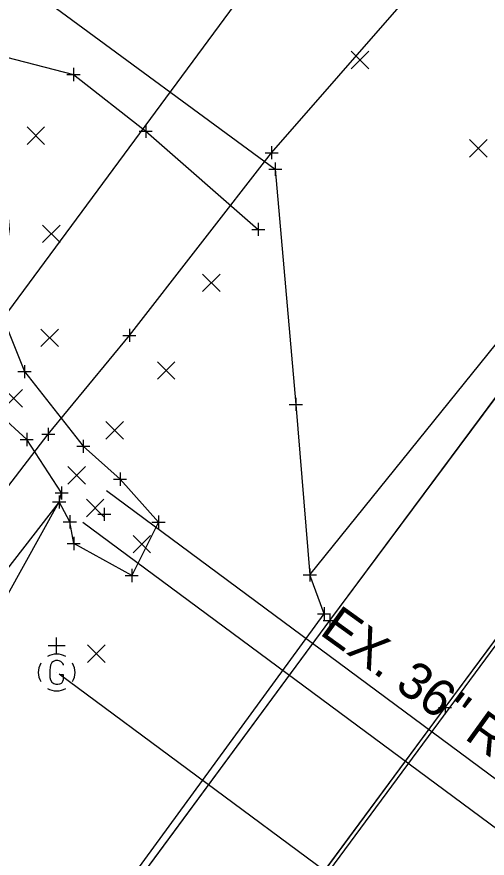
# Model space of a CAD drawing. Extents: x 1324089 to 1329959, y 459099 to 462017.
# Drawn here: x 1325758 to 1325793.8, y 460930.3 to 460994.4 of the extents above; entities that cross this region are included whole.
import ezdxf

# ---------------------------------------------------------------- set-up
doc = ezdxf.new("R2010")
doc.units = 0
for name, color, linetype in [('Default', 7, 'Continuous'), ('DR_X_Storm_Sewer', 7, 'Continuous'), ('PM_X_CL_Double_Solid', 7, 'Continuous'), ('PM_X_Edge_Line', 7, 'Continuous'), ('PM_X_Surveyed_Line', 7, 'Continuous'), ('PV_X_Driveway', 7, 'Continuous'), ('PV_X_EOP', 7, 'Continuous'), ('RW_X_CL', 7, 'Continuous'), ('RW_X_Fee_RW', 7, 'Continuous'), ('SV_X_Break_Lines', 7, 'Continuous'), ('SV_X_Random_Point', 7, 'Continuous'), ('SV_X_Shot_Marker', 7, 'Continuous'), ('UT_X_Gas', 7, 'Continuous'), ('UT_X_Gas_Cells', 7, 'Continuous'), ('UT_X_Telecom', 7, 'Continuous')]:
    doc.layers.add(name, color=color, linetype=linetype)

msp = doc.modelspace()

# ---------------------------------------------------------------- linework, layer by layer
at = {"layer": 'DR_X_Storm_Sewer'}
for p, q in [((1325764.818, 460958.35), (1325814.731, 460921.372)), ((1325763.032, 460955.94), (1325812.945, 460918.961))]:
    msp.add_line(p, q, dxfattribs=at)
at = {"layer": 'PM_X_CL_Double_Solid'}
for p, q in [((1325790.621, 460941.822), (1325811.714, 460970.267)), ((1325771.48, 460915.921), (1325790.621, 460941.822))]:
    msp.add_line(p, q, dxfattribs=at)
at = {"layer": 'PM_X_Edge_Line'}
for p, q in [((1325781.839, 460948.458), (1325803.18, 460977.152)), ((1325762.589, 460922.342), (1325781.839, 460948.458))]:
    msp.add_line(p, q, dxfattribs=at)
at = {"layer": 'PM_X_Surveyed_Line'}
for points in [[(1325476.468, 460534.643), (1325497.311, 460562.916), (1325518.315, 460591.401), (1325539.274, 460619.828), (1325559.79, 460647.383), (1325579.721, 460674.061), (1325600.337, 460701.825), (1325621.689, 460730.614), (1325640.884, 460756.72), (1325660.886, 460784.382), (1325681.351, 460812.314), (1325701.967, 460840.182), (1325722.786, 460868.466), (1325742.91, 460895.719), (1325762.589, 460922.342), (1325781.839, 460948.458), (1325803.18, 460977.152), (1325823.469, 461004.355), (1325843.804, 461031.799), (1325864.413, 461059.129), (1325882.729, 461083.843)], [(1325487.31, 460531.49), (1325505.558, 460556.208), (1325527.376, 460585.354), (1325547.884, 460612.775), (1325568.496, 460640.752), (1325588.531, 460667.691), (1325609.182, 460695.622), (1325629.784, 460723.415), (1325649.854, 460750.691), (1325670.058, 460778.358), (1325689.988, 460805.971), (1325710.726, 460833.831), (1325731.558, 460861.892), (1325751.846, 460889.277), (1325771.48, 460915.921), (1325790.621, 460941.822), (1325811.714, 460970.267), (1325832.154, 460997.962), (1325852.519, 461025.379), (1325872.843, 461052.92), (1325891.559, 461078.179)]]:
    msp.add_lwpolyline(points, dxfattribs=at)
at = {"layer": 'PV_X_Driveway'}
msp.add_lwpolyline([(1325740.02, 461010.738), (1325760.541, 460995.43), (1325777.688, 460982.844), (1325779.255, 460964.921), (1325780.318, 460951.923)], dxfattribs=at)
at = {"layer": 'PV_X_EOP'}
msp.add_lwpolyline([(1325599.851, 460702.278), (1325620.929, 460731.198), (1325640.127, 460757.247), (1325660.195, 460784.818), (1325680.806, 460812.72), (1325701.432, 460840.567), (1325722.312, 460868.776), (1325742.472, 460895.993), (1325762.177, 460922.641), (1325781.401, 460948.968), (1325780.318, 460951.923), (1325801.557, 460978.256), (1325816.225, 460999.305), (1325818.005, 460999.229), (1325822.667, 461005.049), (1325842.969, 461032.462), (1325863.411, 461059.87), (1325881.769, 461084.581), (1325817.824, 460998.906)], dxfattribs=at)
at = {"layer": 'RW_X_CL'}
msp.add_line((1325484.957, 460527.536), (1326057.933, 461303.201), dxfattribs=at)
at = {"layer": 'RW_X_Fee_RW'}
msp.add_line((1325448.762, 460554.274), (1326011.051, 461315.471), dxfattribs=at)
at = {"layer": 'SV_X_Break_Lines'}
for points in [[(1325755.792, 460950.517), (1325747.971, 460958.055), (1325739.888, 460967.035), (1325733.431, 460974.308), (1325738.909, 460981.966), (1325746.102, 460990.388), (1325754.917, 460991.961), (1325762.313, 460990.056), (1325767.82, 460985.73), (1325776.392, 460978.257)], [(1325602.569, 460725.503), (1325611.535, 460737.32), (1325631.624, 460762.971), (1325651.116, 460791.065), (1325670.213, 460817.468), (1325692.281, 460846.55), (1325713.18, 460875.417), (1325733.816, 460902.837), (1325743.825, 460918.052), (1325750.809, 460936.819), (1325754.596, 460945.574), (1325761.22, 460957.492), (1325755.792, 460950.517)]]:
    msp.add_lwpolyline(points, dxfattribs=at)
msp.add_lwpolyline([(1325761.22, 460957.492), (1325761.412, 460958.176), (1325758.753, 460962.25), (1325754.408, 460966.201), (1325747.053, 460971.488), (1325744.168, 460973.186), (1325741.264, 460977.729), (1325743.709, 460980.748), (1325748.637, 460978.595), (1325751.459, 460980.538), (1325750.657, 460983.988), (1325752.818, 460985.149), (1325755.224, 460984.954), (1325757.128, 460981.497), (1325757.411, 460978.28), (1325756.573, 460972.388), (1325758.586, 460967.416), (1325763.061, 460961.728), (1325765.859, 460959.222), (1325768.795, 460955.944), (1325766.752, 460951.889), (1325762.332, 460954.322), (1325762.039, 460955.973)], close=True, dxfattribs=at)
at = {"layer": 'SV_X_Random_Point'}
for p, q in [((1325783.47, 460990.486), (1325784.803, 460991.821)), ((1325783.47, 460991.821), (1325784.803, 460990.486)), ((1325758.778, 460984.721), (1325760.111, 460986.056)), ((1325758.778, 460986.056), (1325760.111, 460984.721)), ((1325792.486, 460983.759), (1325793.819, 460985.094)), ((1325792.486, 460985.094), (1325793.819, 460983.759)), ((1325759.955, 460977.243), (1325761.288, 460978.578)), ((1325759.955, 460978.578), (1325761.288, 460977.243)), ((1325772.153, 460973.517), (1325773.486, 460974.852)), ((1325772.153, 460974.852), (1325773.486, 460973.517)), ((1325759.838, 460969.32), (1325761.172, 460970.655)), ((1325759.838, 460970.655), (1325761.172, 460969.32)), ((1325768.703, 460966.833), (1325770.036, 460968.168)), ((1325768.703, 460968.168), (1325770.036, 460966.833)), ((1325757.085, 460964.722), (1325758.418, 460966.057)), ((1325757.085, 460966.057), (1325758.418, 460964.722)), ((1325764.791, 460962.273), (1325766.125, 460963.608)), ((1325764.791, 460963.608), (1325766.125, 460962.273)), ((1325761.889, 460958.844), (1325763.223, 460960.179)), ((1325761.889, 460960.179), (1325763.223, 460958.844)), ((1325763.303, 460956.367), (1325764.636, 460957.701)), ((1325763.303, 460957.701), (1325764.636, 460956.367)), ((1325766.855, 460953.605), (1325768.188, 460954.94)), ((1325766.855, 460954.94), (1325768.188, 460953.605)), ((1325763.386, 460945.264), (1325764.719, 460946.599)), ((1325763.386, 460946.599), (1325764.719, 460945.264))]:
    msp.add_line(p, q, dxfattribs=at)
at = {"layer": 'SV_X_Shot_Marker'}
for p, q in [((1325762.313, 460990.556), (1325762.313, 460989.556)), ((1325761.813, 460990.056), (1325762.813, 460990.056)), ((1325762.313, 460990.056), (1325762.313, 460990.056)), ((1325767.82, 460986.23), (1325767.82, 460985.23)), ((1325767.32, 460985.73), (1325768.32, 460985.73)), ((1325767.82, 460985.73), (1325767.82, 460985.73)), ((1325776.911, 460984.097), (1325777.911, 460984.097)), ((1325777.411, 460984.597), (1325777.411, 460983.597)), ((1325777.411, 460984.097), (1325777.411, 460984.097)), ((1325777.188, 460982.844), (1325778.188, 460982.844)), ((1325777.688, 460983.344), (1325777.688, 460982.344)), ((1325777.688, 460982.844), (1325777.688, 460982.844)), ((1325775.892, 460978.257), (1325776.892, 460978.257)), ((1325776.392, 460978.757), (1325776.392, 460977.757)), ((1325776.392, 460978.257), (1325776.392, 460978.257)), ((1325766.576, 460970.681), (1325766.576, 460969.681)), ((1325766.076, 460970.181), (1325767.076, 460970.181)), ((1325766.576, 460970.181), (1325766.576, 460970.181)), ((1325758.086, 460967.416), (1325759.086, 460967.416)), ((1325758.586, 460967.916), (1325758.586, 460966.916)), ((1325758.586, 460967.416), (1325758.586, 460967.416)), ((1325778.755, 460964.921), (1325779.755, 460964.921)), ((1325779.255, 460965.421), (1325779.255, 460964.421)), ((1325779.255, 460964.921), (1325779.255, 460964.921)), ((1325760.392, 460963.14), (1325760.392, 460962.14)), ((1325758.253, 460962.25), (1325759.253, 460962.25)), ((1325758.753, 460962.75), (1325758.753, 460961.75)), ((1325758.753, 460962.25), (1325758.753, 460962.25)), ((1325759.892, 460962.64), (1325760.892, 460962.64)), ((1325760.392, 460962.64), (1325760.392, 460962.64)), ((1325763.061, 460962.228), (1325763.061, 460961.228)), ((1325762.561, 460961.728), (1325763.561, 460961.728)), ((1325763.061, 460961.728), (1325763.061, 460961.728)), ((1325765.859, 460959.722), (1325765.859, 460958.722)), ((1325765.359, 460959.222), (1325766.359, 460959.222)), ((1325765.859, 460959.222), (1325765.859, 460959.222)), ((1325761.412, 460958.676), (1325761.412, 460957.676)), ((1325760.912, 460958.176), (1325761.912, 460958.176)), ((1325761.22, 460957.992), (1325761.22, 460956.992)), ((1325761.22, 460957.992), (1325761.22, 460956.992)), ((1325761.412, 460958.176), (1325761.412, 460958.176)), ((1325760.72, 460957.492), (1325761.72, 460957.492)), ((1325760.72, 460957.492), (1325761.72, 460957.492)), ((1325761.22, 460957.492), (1325761.22, 460957.492)), ((1325761.22, 460957.492), (1325761.22, 460957.492)), ((1325762.039, 460956.473), (1325762.039, 460955.473)), ((1325764.161, 460956.552), (1325765.161, 460956.552)), ((1325764.661, 460957.052), (1325764.661, 460956.052)), ((1325764.661, 460956.552), (1325764.661, 460956.552)), ((1325761.539, 460955.973), (1325762.539, 460955.973)), ((1325762.039, 460955.973), (1325762.039, 460955.973)), ((1325768.295, 460955.944), (1325769.295, 460955.944)), ((1325768.795, 460956.444), (1325768.795, 460955.444)), ((1325768.795, 460955.944), (1325768.795, 460955.944)), ((1325762.332, 460954.822), (1325762.332, 460953.822)), ((1325761.832, 460954.322), (1325762.832, 460954.322)), ((1325762.332, 460954.322), (1325762.332, 460954.322)), ((1325766.752, 460952.389), (1325766.752, 460951.389)), ((1325780.318, 460952.423), (1325780.318, 460951.423)), ((1325766.252, 460951.889), (1325767.252, 460951.889)), ((1325766.752, 460951.889), (1325766.752, 460951.889)), ((1325779.818, 460951.923), (1325780.818, 460951.923)), ((1325780.318, 460951.923), (1325780.318, 460951.923)), ((1325781.401, 460949.468), (1325781.401, 460948.468)), ((1325780.901, 460948.968), (1325781.901, 460948.968)), ((1325781.401, 460948.968), (1325781.401, 460948.968)), ((1325781.839, 460948.959), (1325781.839, 460947.959)), ((1325781.339, 460948.458), (1325782.339, 460948.458)), ((1325781.839, 460948.458), (1325781.839, 460948.458)), ((1325790.121, 460941.822), (1325791.121, 460941.822)), ((1325790.621, 460942.322), (1325790.621, 460941.322)), ((1325790.621, 460941.822), (1325790.621, 460941.822))]:
    msp.add_line(p, q, dxfattribs=at)
at = {"layer": 'UT_X_Gas'}
msp.add_line((1325761.232, 460944.395), (1325792.464, 460921.244), dxfattribs=at)
at = {"layer": 'UT_X_Gas_Cells'}
for p, q in [((1325761.033, 460945.898), (1325761.033, 460947.168)), ((1325761.67, 460946.533), (1325760.396, 460946.533)), ((1325761.033, 460944.498), (1325761.033, 460944.498))]:
    msp.add_line(p, q, dxfattribs=at)
msp.add_lwpolyline([(1325761.566, 460945.044), (1325761.552, 460945.115), (1325761.509, 460945.185), (1325761.438, 460945.256), (1325761.339, 460945.341), (1325761.268, 460945.37), (1325761.211, 460945.384), (1325761.126, 460945.398), (1325760.956, 460945.398), (1325760.886, 460945.384), (1325760.843, 460945.37), (1325760.786, 460945.341), (1325760.673, 460945.256), (1325760.602, 460945.157), (1325760.559, 460945.044), (1325760.531, 460944.888), (1325760.503, 460944.661), (1325760.503, 460944.363), (1325760.517, 460944.123), (1325760.574, 460943.938), (1325760.659, 460943.768), (1325760.73, 460943.711), (1325760.815, 460943.655), (1325760.971, 460943.598), (1325761.126, 460943.598), (1325761.282, 460943.626), (1325761.339, 460943.655), (1325761.396, 460943.683), (1325761.452, 460943.74), (1325761.509, 460943.825), (1325761.566, 460943.953), (1325761.566, 460944.307), (1325761.268, 460944.307)], dxfattribs=at)
for start, end in [(60.01836, 120.01574), (150.01836, 209.98164), (330.01836, 29.98164), (239.98426, 299.98164)]:
    msp.add_arc((1325761.033, 460944.498), 1.4, start, end, dxfattribs=at)
at = {"layer": 'UT_X_Telecom'}
msp.add_lwpolyline([(1325738.74, 460932.483), (1325743.645, 460940.13), (1325749.252, 460948.815), (1325753.874, 460954.188), (1325760.392, 460962.64), (1325766.576, 460970.181), (1325777.411, 460984.097), (1325792.957, 461001.921)], dxfattribs=at)

# ---------------------------------------------------------------- texts
at = {"layer": 'Default'}
msp.add_text('EX. 36" RCP', height=2.8, rotation=324.19138, dxfattribs=at).set_placement((1325780.981, 460947.453))

doc.saveas('drawing.dxf')
